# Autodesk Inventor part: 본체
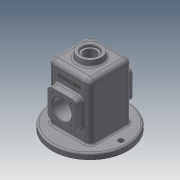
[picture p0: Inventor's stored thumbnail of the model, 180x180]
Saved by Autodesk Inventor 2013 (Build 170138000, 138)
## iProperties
Created: 2021-08
Part Number: 본체
Material: 일반
Document SubType Name: Modeling
Designer: kum
Density: 1 g/cm^3
Author: kum
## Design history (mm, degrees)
sketch "스케치1"
  geometry: L1 (-37, 37)-(37, 37); L2 (37, 37)-(37, -37); L3 (37, -37)-(-37, -37); L4 (-37, -37)-(-37, 37); L5 (-37, 37)-(37, -37); L6 (37, 37)-(-37, -37); 1 further point
  constraints: 12 end point, 2 midpoint, 2 parallel, 1 horizontal, 1 perpendicular
  dimensions: "d0" = 74 distance of L2.end L3.end; "d1" = 74 distance of L1.end L2.end
extrude "돌출1" new body sketch "스케치1" distance "d2" = 110; taper "d3" = 0 deg
feature "쉘1" dims "d6" = 5
sketch "스케치3"
  geometry: L1 (37, 37)-(-37, 37) reference; L2 (-37, 37)-(-37, -37) reference; L3 (-37, -37)-(37, -37) reference; L4 (37, -37)-(37, 37) reference; C1 r 67 at (0, 0); 1 further point
  constraints: 1 centre point, 1 coincident
  dimensions: "d7" = 134 diameter of C1
extrude "돌출2" join sketch "스케치3" distance "d8" = 10; taper "d9" = 0 deg
sketch "스케치4"
  geometry: L1 (37, 37)-(-37, 37) reference; L2 (0, 0)-(55, 0); C1 r 67 at (0, 0) reference; C2 r 4.5 at (55, 0)
  constraints: 2 end point, 1 centre point, 1 coincident, 1 parallel
  dimensions: "d10" = 55 distance of L2.start L2.end; "d11" = 9 diameter of C2
extrude "돌출3" cut sketch "스케치4" stored distance "d12" = 10; taper "d13" = 0 deg
sketch "스케치6"
  geometry: L1 (0, -100)-(0, 0) reference; L2 (37, -110)-(37, -55); L3 (12, -30)-(62, -30); L4 (62, -30)-(62, -80); L5 (62, -80)-(12, -80); L6 (12, -80)-(12, -30); L7 (12, -30)-(62, -80); L8 (62, -30)-(12, -80)
  constraints: 14 end point, 3 parallel, 2 midpoint, 1 horizontal, 1 perpendicular
  dimensions: "d14" = 55 distance of L2.start L2.end; "d15" = 50 distance of L4.end L5.end; "d16" = 50 distance of L3.end L4.end
extrude "돌출4" join sketch "스케치6" distance "d17" = 13; taper "d18" = 0 deg
sketch "스케치8"
  geometry: L1 (20, -38)-(54, -38); L2 (54, -38)-(54, -72); L3 (20, -72)-(20, -38); L4 (20, -38)-(54, -72); L5 (54, -38)-(20, -72); L6 (104, -110)-(-30, -110) reference; L7 (37, -110)-(37, -55); L8 (5, -110)-(69, -110) reference; L9 (20, -72)-(54, -72); 6 further points
  constraints: 14 end point, 6 midpoint, 4 coincident, 2 parallel, 2 perpendicular, 1 horizontal, 1 horizontal alignment, 1 vertical alignment
  dimensions: "d23" = 34 distance of L2.end L3.start; "d24" = 34 distance of L1.end L2.end; "d64" = 55 distance of L7.start L7.end
hole "구멍1" sketch "스케치8" at (20, -38), (20, -72), (54, -72), (54, -38) diameter "d25" = 3.242; stored, may be unused: countersink angle "d29" = 90 deg, drill point angle "d31" = 118 deg; dims "d26" = 8, "d27" = 4, "d28" = 2, "d30" = 10
node "작업 평면1"
sketch "스케치10"
  geometry: C1 r 20 at (0, 0); 1 further point
  constraints: 1 centre point, 1 coincident
  dimensions: "d33" = 40 diameter of C1
extrude "돌출6" join sketch "스케치10" stored distance "d34" = 13; taper "d35" = 6 deg
sketch "스케치11"
  geometry: C1 r 20 at (0, 0) reference; 1 further point
  constraints: 1 coincident
hole "구멍2" sketch "스케치11" at (0, 0) diameter "d36" = 21; stored, may be unused: countersink angle "d40" = 90 deg, drill point angle "d42" = 118 deg; dims "d37" = 8, "d38" = 28, "d39" = 4, "d41" = 10
sketch "스케치12"
  geometry: L1 (64, 0)-(64, -105) reference; L2 (32, -55)-(32, 0); C1 r 25 at (32, -55)
  constraints: 2 end point, 1 centre point, 1 parallel
  dimensions: "d43" = 50 diameter of C1; "d60" = 55 distance of L2.end L2.start
extrude "돌출7" join sketch "스케치12" distance "d44" = 7; taper "d45" = -20 deg
sketch "스케치15"
  geometry: C1 r 22.452 at (0, 0) reference; C2 r 17 at (0, 0); 1 further point
  constraints: 1 centre point, 1 coincident
  dimensions: "d61" = 34 diameter of C2
extrude "돌출8" cut sketch "스케치15" stored distance "d62" = 7; taper "d63" = 0 deg
fillet "모깎기1" dims "d46" = 3
fillet "모깎기2" dims "d47" = 8
fillet "모깎기3" dims "d48" = 8
fillet "모깎기4" dims "d49" = 8
fillet "모깎기5" dims "d50" = 3
fillet "모깎기6" dims "d51" = 3
fillet "모깎기7" dims "d52" = 3
chamfer "모따기1" distance "d53" = 1; stored, may be unused: second distance "d54" = 2, angle "d55" = 45 deg
sketch "스케치14"
  geometry: L1 (9, 18)-(49, 18) reference; L2 (-8, 0)-(-8, -89) reference; 2 further points
  constraints: 1 other
  dimensions: "d56" = 28 distance from line of L1 point (29, -10); "d57" = 37 distance from line of L2 point (29, -10)
feature "엠보싱1" sketch "스케치14" dims "d0" = 74, "d1" = 74, "d58" = 0.5, "d59" = 0
chamfer "모따기2" distance "d65" = 1; stored, may be unused: second distance "d66" = 2, angle "d67" = 45 deg
node "솔리드1"
mirror "대칭1"
mirror "대칭2"
mirror "대칭3"
